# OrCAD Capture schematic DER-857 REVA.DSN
size Custom
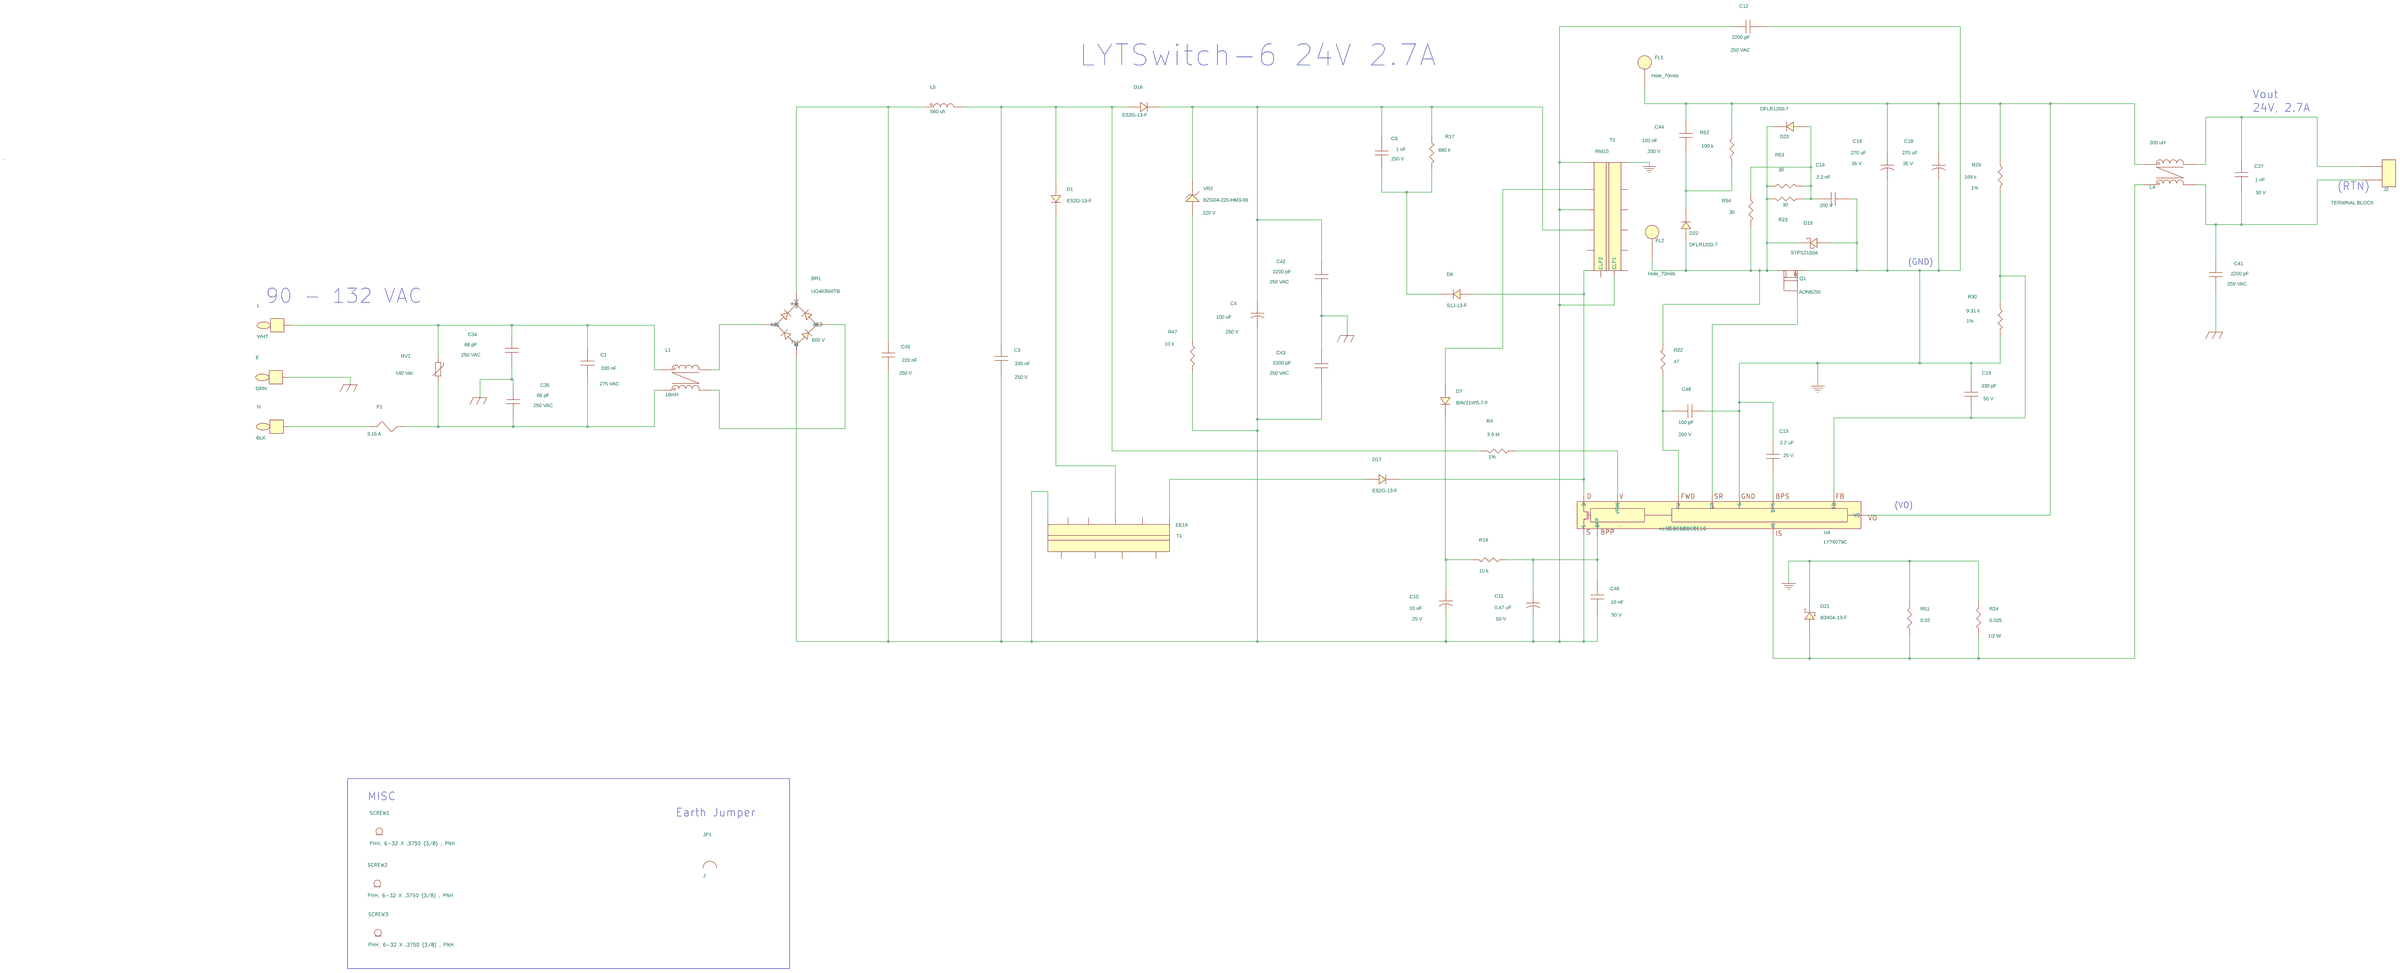
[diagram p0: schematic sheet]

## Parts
BR1  UG4KB60TB  [pidaxbridgeD3K]
C1  330 nF  [pinp_xcaprad15x8p5x14Hd040]
C3  330 nF  [pinpcr511x300ls393d40]
C4  100 uF  [pipolcapclyd630ls300040]
C9  1 nF  [pismc0805]
C10  10 uF  [pipolcapclyd200ls80030]
C11  0.47 uF  [pipolcapclyd200ls80030]
C12  2200 pF  [pinpcaprad9p0D10p0LS030]
C13  2.2 uF  [pismc1206]
C14  2.2 nF  [pismc0805]
C16  270 uF  [pipolcapclyd320ls140030]
C18  270 uF  [pipolcapclyd320ls140030]
C19  330 pF  [pismc0805]
C34  68 pF  [pinpycaprad470x210ls380040]
C35  68 pF  [pinpycaprad470x210ls380040]
C37  1 nF  [pinpcaprad200x100200030]
C41  2200 pF  [pinpcaprad9p0D10p0LS030]
C42  2200 pF  [pinpcaprad9p0D10p0LS030]
C43  2200 pF  [pinpcaprad9p0D10p0LS030]
C44  100 nF  [pismc1206]
C45  220 nF  [pi_np_cap_rad386x197x295x030]
C46  10 nF  [pismc0805]
C48  100 pF  [pismc0805]
D1  ES2G-13-F  [pismdo214aa12]
D7  BAV21WS-7-F  [pismsod323]
D8  S1J-13-F  [pismdsma]
D16  ES2G-13-F  [pismdo214aa12]
D17  ES2G-13-F  [pismdo214aa12]
D18  STPS2150A  [pismdo214ac12]
D21  B340A-13-F  [pismdo214ac12]
D22  DFLR1200-7  [pismddflr120012]
D23  DFLR1200-7  [pismddflr120012]
E  GRN  [pitpkeystone125x125]
F1  3.15 A  [pi_rst_microfuse]
FL1  Hole_70mils  [pi_hole_70mil]
FL2  Hole_70mils  [pi_hole_70mil]
J2  TERMINAL BLOCK  [pi_term_block_2pin_ls200]
JP1  J  [pi_jumper4000]
L  WHT  [pitpkeystone125x125]
L1  18mH  [pi_CMC_18mH_Sumida]
L4  200 uH  [pi_toroid_DER742CMCL4]
L5  560 uh  [pi_choke_RL5480-5_d2]
N  BLK  [pitpkeystone125x125]
Q1  AON6250  [pismpqfn5x6b]
R4  3.9 M  [pismr1206]
R17  680 k  [pismr0805]
R18  10 k  [pismr0805]
R22  47  [pismr1206]
R23  30  [pismr1206]
R24  0.025  [pismr1206]
R29  169 k  [pismr0805]
R30  9.31 k  [pismr0805]
R47  10 k  [pismr0805]
R51  0.02  [pismr0805]
R52  100 k  [pismr0805]
R53  30  [pismr1206]
R54  30  [pismr1206]
RV1  140 Vac  [pidisc500x225ls335x140040]
SCREW1  PHH, 6-32 X .3750 (3/8) , PNH
SCREW2  PHH, 6-32 X .3750 (3/8) , PNH
SCREW3  PHH, 6-32 X .3750 (3/8) , PNH
T1  EE19  [pi_bobbin_ee19_10p]
T2  RM10  [pi_bobbin_rm-10_12p_clp]
U4  LYT6079C  [pi_ic_insop_24d]
VR2  BZG04-220-HM3-08  [pismdo214ac12]

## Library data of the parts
BR1 = DISCRETE_BRIDGE_+~~-: ALT_SYMBOLS: pidaxbridgeD3K_horz; Disp_Voltage: 600 V; FPLIST: pidaxbridgeD3K,pidaxbridgeD3K_horz; Part Number: 15-01330-00
C1 = CAP_NP: ALT_SYMBOLS: pinp_xcaprad15x8p5x14Hd040H; Disp_Voltage: 275 VAC; FPLIST: pinp_xcaprad15x8p5x14Hd040,pinp_xcaprad15x8p5x14Hd040H; Part Number: 20-09095-00; Voltage: 275 VAC
C3 = CAP_NP: Disp_Voltage: 250 V; Part Number: 20-01321-00; Voltage: 250 V
C4 = CAP_POL: ALT_SYMBOLS: pipolcapclyd7p5ls16x21p5D040h; Disp_Voltage: 250 V; FPLIST: pipolcapclyd630ls300040,pipolcapclyd7p5ls16x21p5D040h; Part Number: 20-09212-00; Voltage: 250 V
C9 = CAP_NP: Disp_Voltage: 250 V; Part Number: 20-00736-00; Voltage: 250 V
C10 = CAP_POL: ALT_SYMBOLS: pipolcapclyd200ls80030h; Disp_Voltage: 25 V; FPLIST: pipolcapclyd200ls80030,pipolcapclyd200ls80030h; Part Number: 20-01182-00; Voltage: 25 V
C11 = CAP_POL: ALT_SYMBOLS: pipolcapclyd5p0x12p5ls2p0d30h; Disp_Voltage: 50 V; FPLIST: pipolcapclyd200ls80030,pipolcapclyd5p0x12p5ls2p0d30h; Part Number: 20-09221-00; Voltage: 50 V
C12 C41-C43 = CAP_NP: Disp_Voltage: 250 VAC; Part Number: 20-09158-00; Voltage: 250 VAC
C13 = CAP_NP: Disp_Voltage: 25 V; Part Number: 20-01034-00; Voltage: 25 V
C14 = CAP_NP: Disp_Voltage: 200 V; Part Number: 20-00761-00; Voltage: 200 V
C16 C18 = CAP_POL: ALT_SYMBOLS: pipolcapclyd320ls140d30h750; COMPGROUP: 3; Disp_Voltage: 35 V; FPLIST: pipolcapclyd320ls140030,pipolcapclyd320ls140030430h,pipolcapclyd320ls140d30h750; Part Number: 20-00045-00; Voltage: 35 V
C19 = CAP_NP: Disp_Voltage: 50 V; Part Number: 20-09189-00; Voltage: 50 V
C34 C35 = CAP_NP: Disp_Voltage: 250 VAC; Part Number: 20-00557-00; Voltage: 250 VAC
C37 = CAP_NP: Disp_Voltage: 50 V; Part Number: 20-01057-00; Voltage: 50 V
C44 = CAP_NP: Disp_Voltage: 200 V; Part Number: 20-00918-00; Voltage: 200 V
C45 = CAP_NP: Disp_Voltage: 250 V; Part Number: 20-08949-00; Voltage: 250 V
C46 = CAP_NP: Disp_Voltage: 50 V; Part Number: 20-00965-00; Voltage: 50 V
C48 = CAP_NP: Disp_Voltage: 200 V; Part Number: 20-00760-00; Voltage: 200 V
D1 D17 = DIODE: COMPGROUP: 1; Part Number: 15-01075-00
D7 = DIODE: Part Number: 15-00385-00
D8 = DIODE: Part Number: 15-01034-00
D16 = DIODE: Part Number: 15-01075-00
D18 = DIODE_SCHOTTKY: Part Number: 15-01334-00
D21 = DIODE_SCHOTTKY: Part Number: 15-01172-00
D22 D23 = DIODE: Disp_Voltage: 200 V; Part Number: 15-01019-00
E = TESTPOINT: Part Number: 35-00187-00
F1 = FUSE: ALT_SYMBOLS: pirstmicrofusehoz; FPLIST: pi_rst_microfuse,pirstmicrofusehoz; Part Number: 40-00071-00; Voltage: 250 V
FL1 FL2 = FlyingLead: Part Number: 35-00282-00
J2 = CON2: Part Number: 35-00277-00
JP1 = JUMPER_1: Part Number: 65-00079-00
L = TESTPOINT: Part Number: 35-00044-00
L1 = TORRID_4P_12_43a: ALT_SYMBOLS: pi_CMC_18mH_Sumida_H; FPLIST: pi_CMC_18mH_Sumida,pi_CMC_18mH_Sumida_H; Part Number: 30-00462-00
L4 = TORRID_4P_13_24: Part Number: 32-00373-00
L5 = INDUCTOR_DOT2: ALT_SYMBOLS: pi_choke_RL5480-5H_d2; FPLIST: pi_choke_RL5480-5_d2,pi_choke_RL5480-5H_d2; Part Number: 30-00317-00
N = TESTPOINT: Part Number: 35-00042-00
Q1 = FET_N_SGD_123_4_5678: Part Number: 50-00167-00
R4 = R: Disp_Tol: 1%; Part Number: 05-06440-00
R17 = R: Part Number: 05-01587-00
R18 R47 = R: Part Number: 05-01543-00
R22 = R: Part Number: 05-01320-00
R23 R53 R54 = R: Part Number: 05-01315-00
R24 = R: Disp_Power: 1/2 W; Disp_Tol: 1%; Part Number: 05-06301-00
R29 = R: Disp_Tol: 1%; Part Number: 05-00802-00
R30 = R: Disp_Tol: 1%; Part Number: 05-03307-00
R51 = R: Disp_Tol: 1%; Part Number: 05-05450-00
R52 = R: Part Number: 05-01567-00
RV1 = VARISTOR: Part Number: 85-00002-00
SCREW1-SCREW3 = SCR_6-32: Part Number: 75-00009-00
T1 = BEE19_10P_TF1939: Part Number: 25-00924-00
T2 = BRM10_12P_PINS: FPLIST: pi_bobbin_rm-10_12p_clp,   *pi_bobbin_rm-10_12p*; Part Number: 25-00905-00
U4 = LYT6: Part Number: 10-01227-00
VR2 = DIODE_ZENER: Disp_Voltage: 220 V; Part Number: 15-01333-00

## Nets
GND: C12.2 C13.1 C14.2 C16.2 C18.2 C19.1 C48.1 D18.2 D21.1 Q1.1(S) R24.2 R30.2 R51.2 T2.1 U4.2(G)
GND_EARTH: C34.2 C35.1 C41.2 C42.2 C43.1 E.1
NC8: U4.8(NC8)
NC9: U4.9(NC9)
NC10: U4.10(NC10)
NC11: U4.11(NC11)
NC12: U4.12(NC12)
NC15: U4.15(nc15)
N10967118: C10.1 D7.1 R18.1
N10967272: D8.2 D17.1 T2.4 U4.24(D)
N10967292: C4.1 C9.2 C42.1 D16.1 R17.1 T2.6 VR2.1
N10967352: C11.1 C46.1 R18.2 U4.14(BPP)
N10967360: C19.2 R29.2 R30.1 U4.3(FB)
N10967588: C16.1 C18.1 C44.1 FL1.1 L4.2 R29.1 R52.1 U4.6(VO)
N10967640: D18.1 D22.2 D23.1 FL2.1 Q1.5(D) R22.2 R23.1 R53.2 R54.2
N10968210: C14.1 D23.2 R23.2 R53.1 R54.1
N10968562: BR1.4(-DC) C3.2 C4.2 C10.2 C11.2 C12.1 C43.2 C45.2 C46.2 R47.2 T1.1 T2.7 T2.9 T2.14(CLP1) U4.16(S)
N10971255: BR1.3(AC2) L1.2
N10975943: C9.1 D8.1 R17.2
N11015169: Q1.4(G) U4.5(SR)
N11207739: C1.1 C34.1 L.1 L1.4 RV1.2
N11207756: C1.2 C35.2 F1.2 L1.1 RV1.1
N11317958: R4.1 U4.13(VPIN)
N11319179: C13.2 U4.4(BPS)
N11459390: C3.1 D1.2 D16.2 L5.1 R4.2
N11460031: BR1.1(+DC) C45.1 L5.2
N11465077: F1.1 N.1
N11478836: R47.1 VR2.2
N11926309: C37.2 C41.1 J2.1 L4.3
N11926313: C37.1 J2.2 L4.4
N11931425: D7.2 T2.8
N11945881: D21.2 L4.1 R24.1 R51.1 U4.1(IS)
N12237173: D17.2 T1.6
N12296601: BR1.2(AC1) L1.3
N12434563: C44.2 D22.1 R52.2
N12457252: D1.1 T1.4
N12494744: C48.2 R22.1 U4.7(FW)

Not connected (* = marked no-connect by the designer): JP1 1 2; Q1 2(S2) 3(S3) 6(D6) 7(D7) 8(D8); T1 2 3 5 7 8 9 10; T2 2 3 5 10 11 12 13(CLP2)

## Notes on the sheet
- LYTSwitch-6 24V 2.7A
- Vout
- 24V, 2.7A
- (RTN)
- (GND)
- 90 - 132 VAC
- (VO)
- MISC
- Earth Jumper
